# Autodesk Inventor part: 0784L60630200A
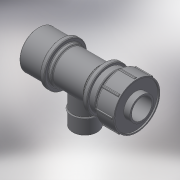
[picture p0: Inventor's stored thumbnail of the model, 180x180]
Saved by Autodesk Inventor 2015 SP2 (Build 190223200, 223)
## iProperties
Created: 2018-02
Part Number: 0784L60630200A
Material: Generic
Description: PLASSON MODULAR MALE TEE 63-2"-63
Document SubType Name: Modeling
Designer: KIM
Density: 1 g/cm^3
Appearance: Default
Author: KIM
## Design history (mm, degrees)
derived "0784L6.ipt"
feature "Solid1::0784L6.ipt"
feature "Solid2::0784L6.ipt"
tag "TaggingFeature1"
body "Solid1"
other parameters: "d26" = 38.55665, "d51" = 2, "d52" = 5.65, "d54" = 0, "d55" = 2, "d56" = 1, "d58" = 360 deg, "d60" = 1, "d63" = 1, "d65" = 0, "d67" = 0, "d69" = 214, "d70" = 92, "d71" = 59.614, "d72" = 63, "d73" = 109.61, "d76" = 103.96, "d77" = 46, "d79" = 58.59, "d80" = 53.55, "d81" = 63, "d82" = 8, "d83" = 101.7, "d84" = 101.7, "d86" = 84.75, "d88" = 90.4, "d89" = 79.1, "d90" = 11.5, "d91" = 43.7, "d92" = 96.05, "d93" = 50.6, "d94" = 41.4, "d95" = 9.2, "d96" = 62.1, "d97" = 64.2, "d98" = 79.1, "d99" = 56.5, "d100" = 50.85, "d101" = 26, "d102" = 44.7105, "d103" = 65.5754, "d104" = 28.6, "E_" = 113, "H_" = 214, "l_1" = 46, "l_2" = 26, "A_" = 92, "d_" = 1, "R_" = 59.614, "SOD_" = 63
